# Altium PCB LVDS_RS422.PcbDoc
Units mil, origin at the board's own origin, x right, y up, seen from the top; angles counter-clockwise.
Board outline 3925 x 2090 mil, 4 copper layers (Top Layer, GROUND, VCC, Bottom Layer); 100 components, 102 nets, 610 pads, 149 vias.
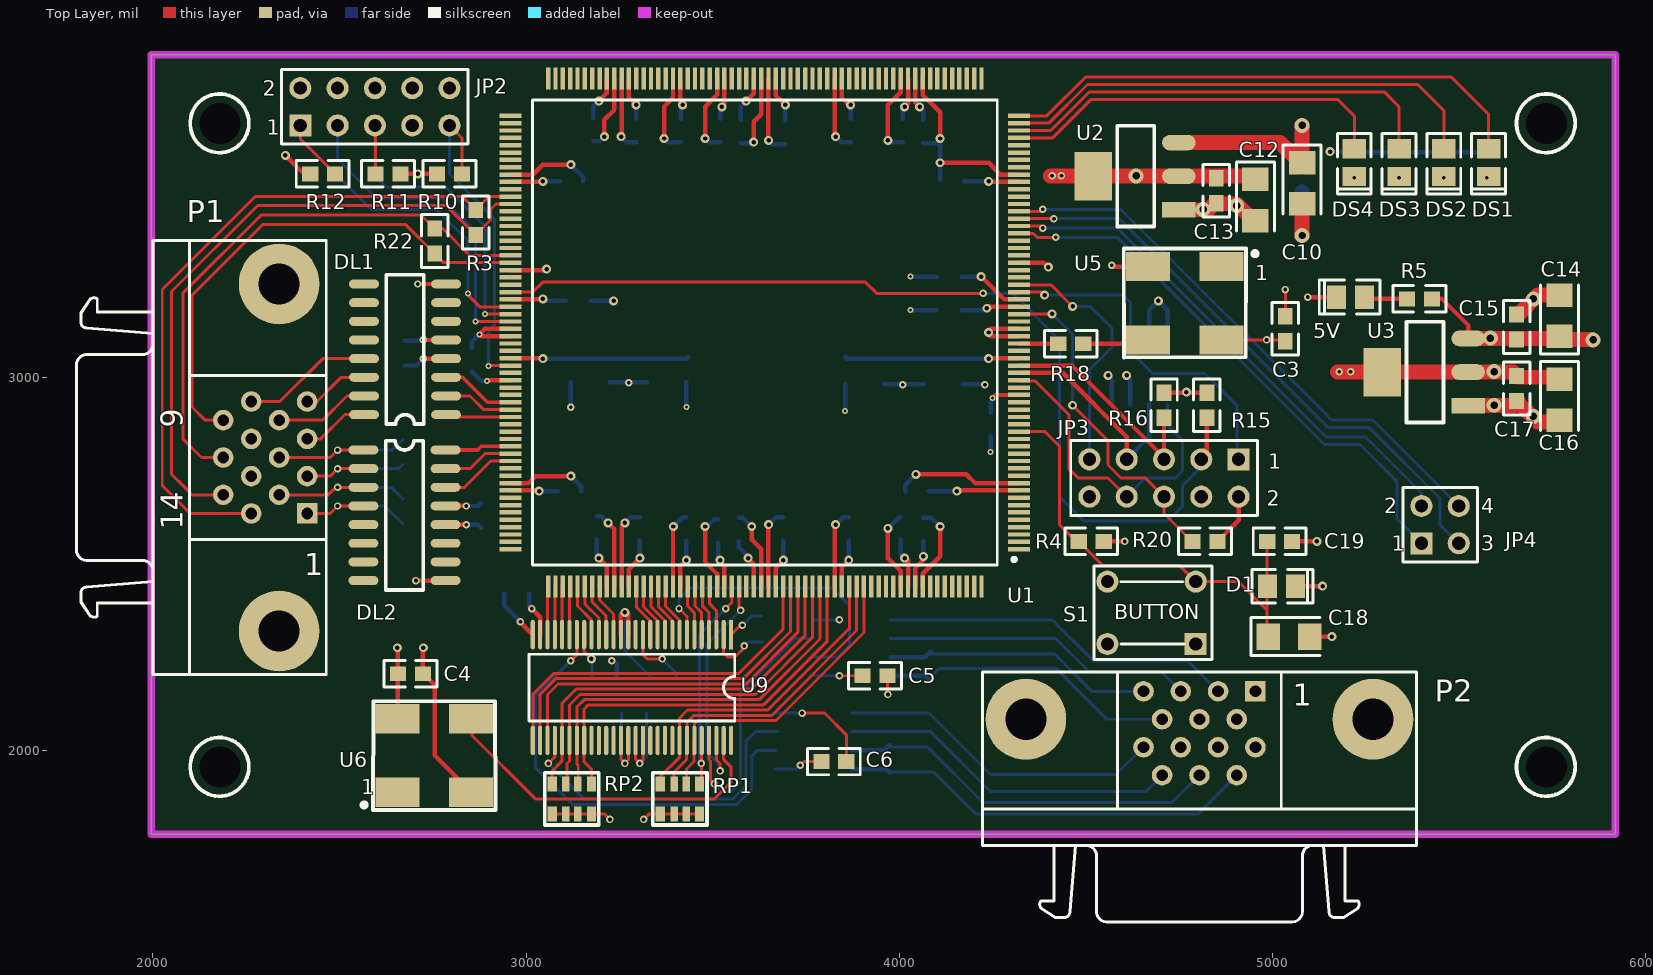
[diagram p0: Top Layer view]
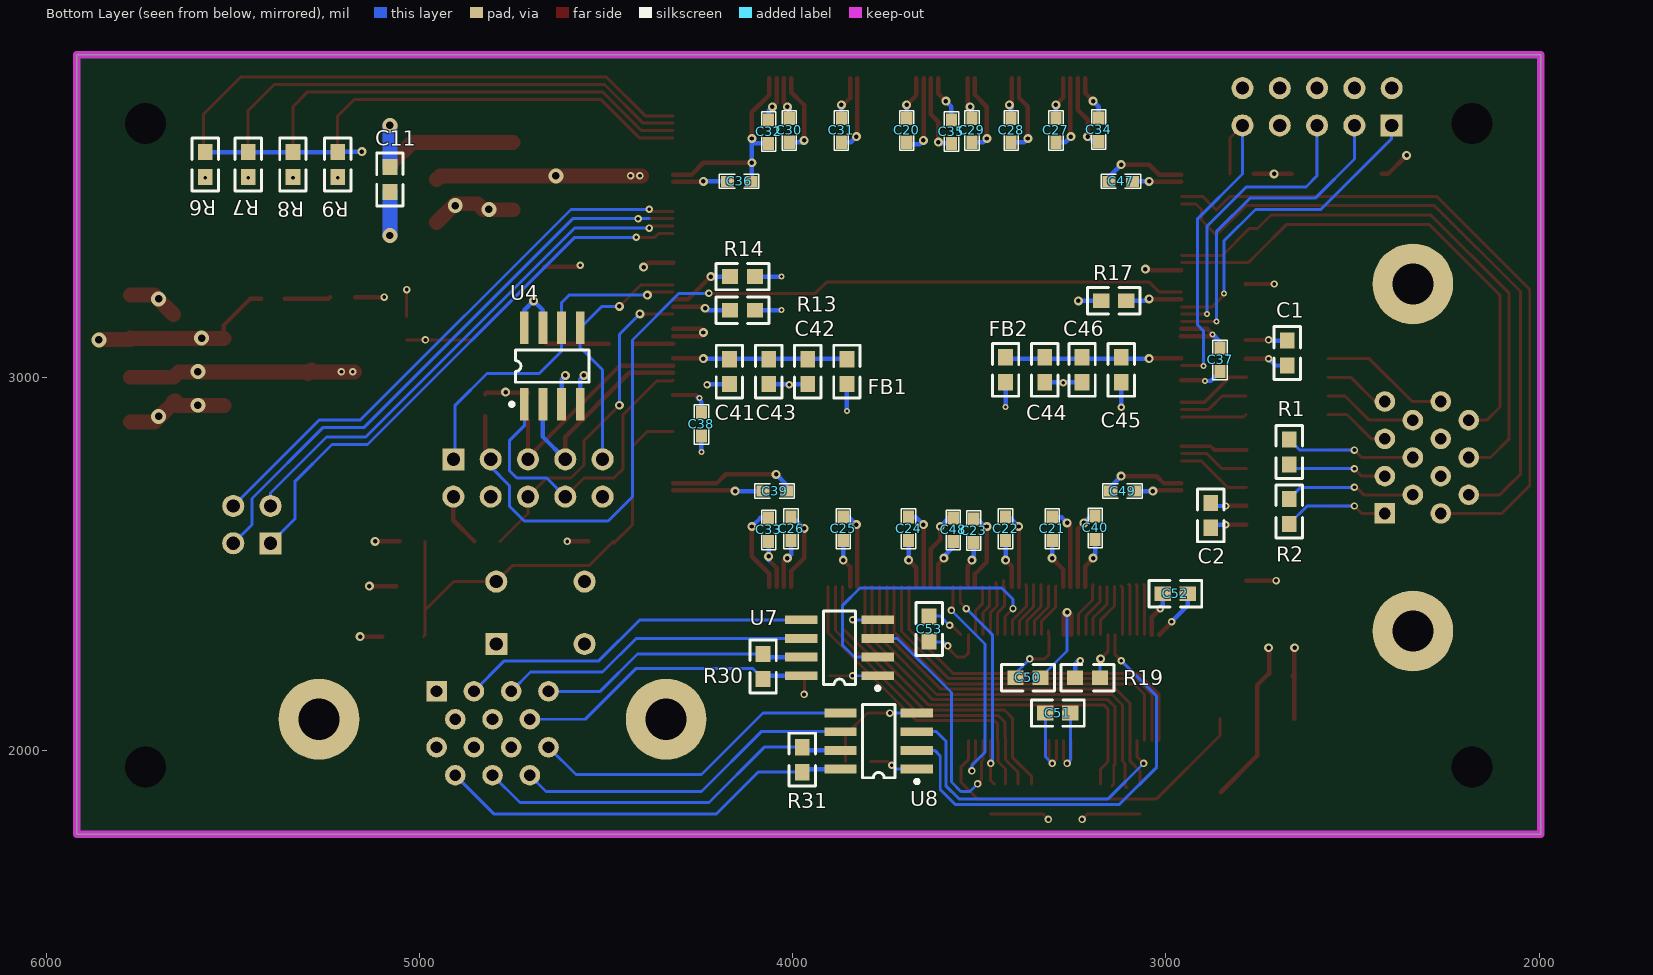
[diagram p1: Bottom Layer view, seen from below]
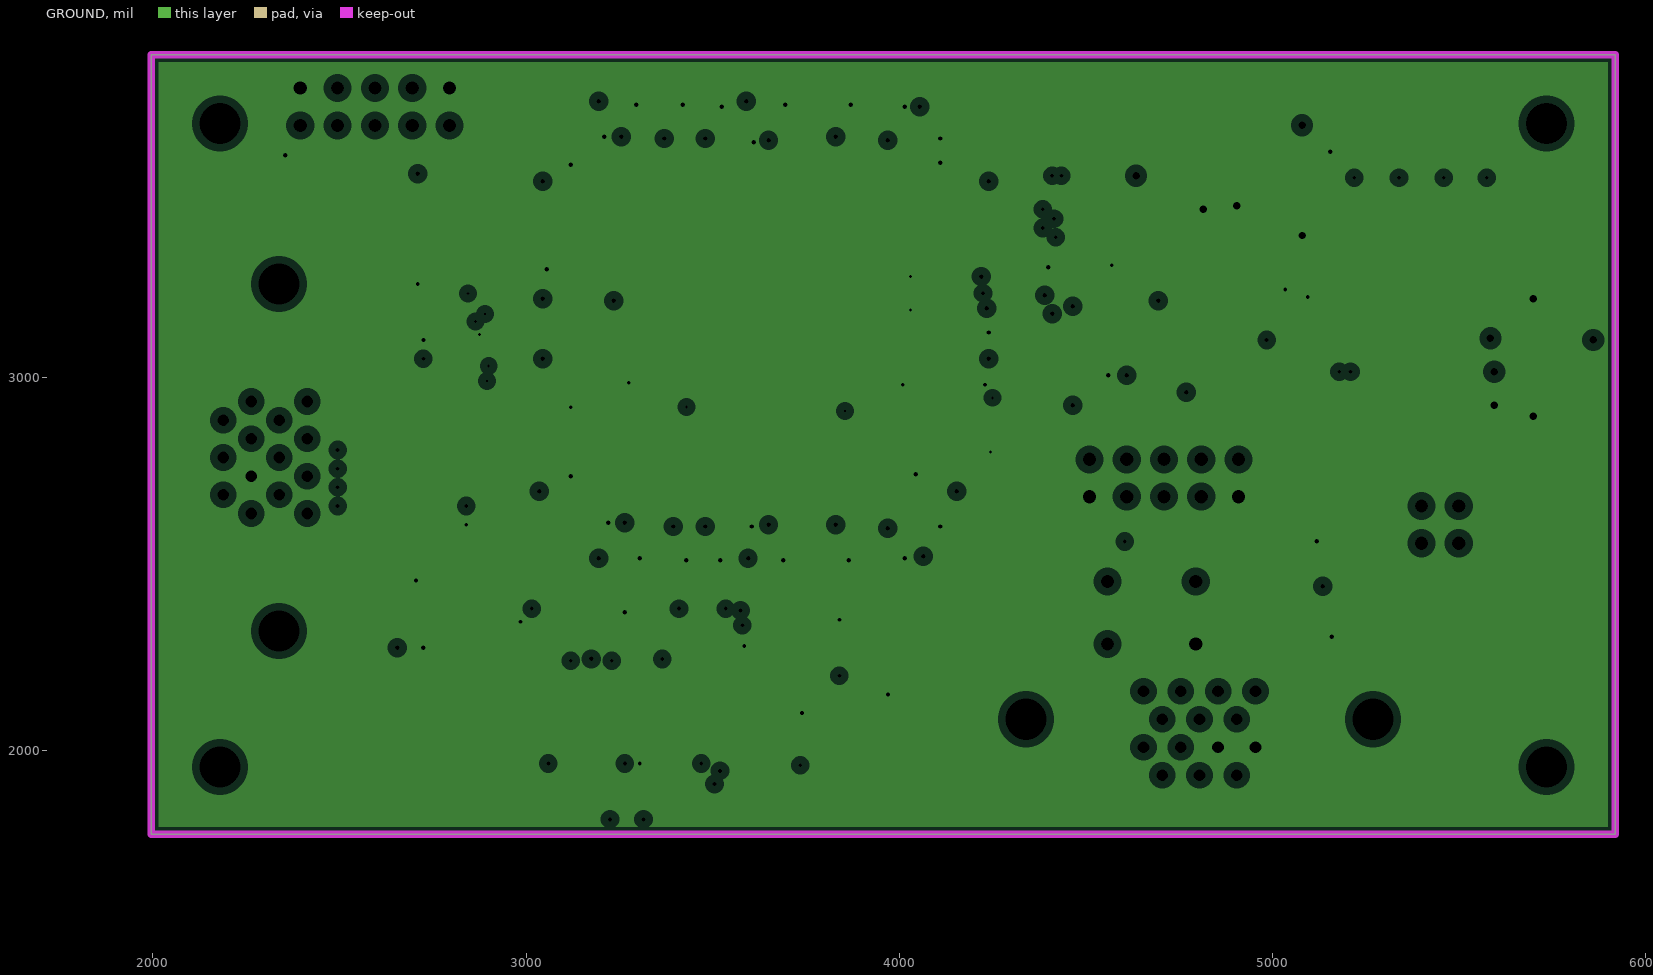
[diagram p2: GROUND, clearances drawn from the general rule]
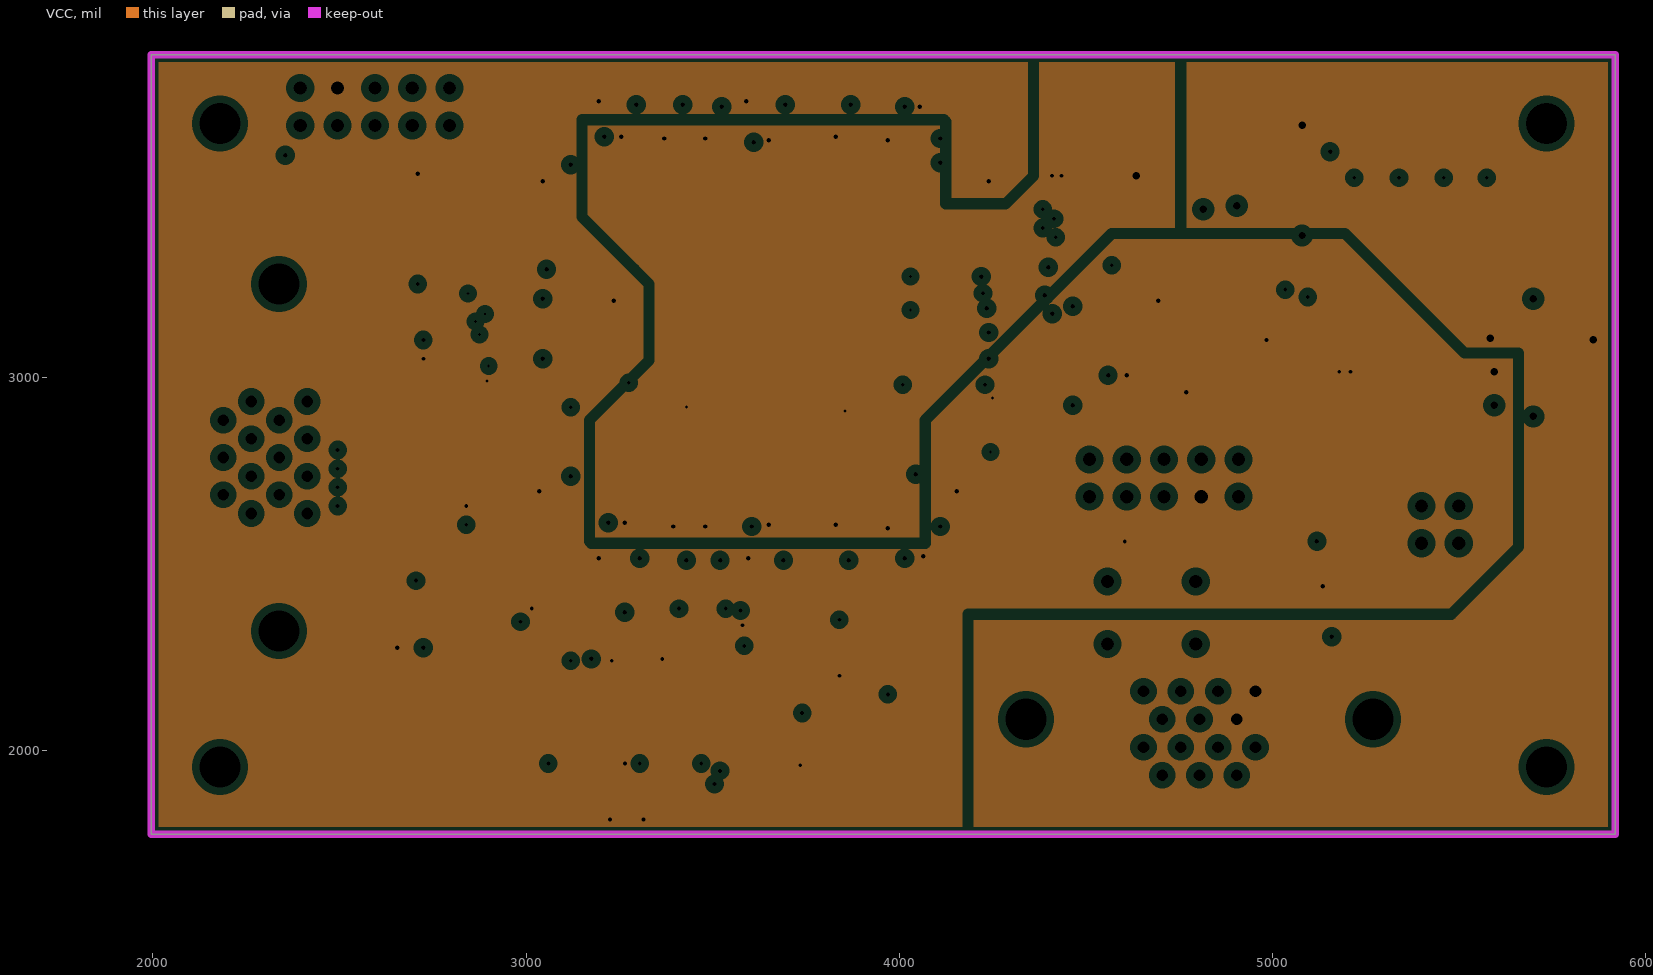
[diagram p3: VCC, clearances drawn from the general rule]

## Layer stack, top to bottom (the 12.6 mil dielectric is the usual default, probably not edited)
Top Layer: signal copper 1.4
Dielectric: core 12.6, FR-4, Dk 4.8
GROUND: plane copper 1.4, net GND
Dielectric: prepreg 12.6, FR-4, Dk 4.8
VCC: plane copper 1.4, net (Multiple Nets)
Dielectric: core 12.6, FR-4, Dk 4.8
Bottom Layer: signal copper 1.4

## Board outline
1995,1775 5920,1775 5920,3865 1995,3865

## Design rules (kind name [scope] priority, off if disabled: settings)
Clearance [All] p1: gap=6
PlaneClearance [All] p1: clearance=20
PlaneConnect [All] p1: planeconnectstyle=Relief reliefexpansion=20 reliefentries=4 reliefconductorwidth=10 reliefairgap=10
PolygonConnect [All] p1: connectstyle=Relief reliefconductorwidth=10 reliefentries=4 polygonreliefangle="90 Angle"
RoutingVias [All] p1: holewidth=28 width=50 viastyle="Through Hole" minholewidth=28 minwidth=50 maxholewidth=28 maxwidth=50
SilkscreenOverComponentPads [All] p1: minsilkscreentomaskgap=10
SolderMaskExpansion [All] p1: expansion=4
TestPointUsage FabricationTestPointUsage [All] p1: valid=0 allowmultiple=FALSE
Testpoint FabricationTestpoint [All] p1: side=3 testpointundercomponent=TRUE minsize=40 maxsize=100 preferedsize=60 minholesize=0 maxholesize=40 preferedholesize=32 testpointgrid=1 style=297 order=0-112345678
Width [All] p1: maxlimit=50 minlimit=6 preferedwidth=10
21 further rules are at their usual default settings.

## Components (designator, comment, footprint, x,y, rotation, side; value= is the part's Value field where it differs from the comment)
5V "LED3" "SMD _LED" 5210,3215 r0 top (schematic designator DS5)
C1 "0.1uF" C1608-0603 2675,3065 r90 bottom
C2 "0.1uF" C1608-0603 2880,2630 r270 bottom
C3 "Cap" C1608-0603 5035,3130 r270 top
C4 "0.1uF" C1608-0603 2690,2205 r0 top
C5 "0.1uF" C1608-0603 3935,2200 r0 top
C6 "0.1uF" C1608-0603 3825,1970 r0 top
C10 "Cap Pol1" CC3216-1206 5080,3520 r270 top
C11 "Cap" C1608-0603 5080,3530 r90 bottom
C12 "Cap Pol1" CC3216-1206 4955,3475 r270 top
C13 "Cap" C1608-0603 4850,3500 r90 top
C14 "Cap Pol1" CC3216-1206 5770,3165 r90 top
C15 "Cap" C1608-0603 5655,3135 r270 top
C16 "Cap Pol1" CC3216-1206 5770,2940 r270 top
C17 "Cap" C1608-0603 5655,2970 r90 top
C18 "22uF" CC3216-1206 5045,2305 r0 top
C19 "0.1uF" C1608-0603 5020,2560 r180 top
C20 "Cap" 0603 3695,3630 r90 bottom
C21 "Cap" 0603 3305,2625 r270 bottom
C22 "Cap" 0603 3430,2625 r270 bottom
C23 "Cap" 0603 3515,2620 r270 bottom
C24 "Cap" 0603 3690,2625 r270 bottom
C25 "Cap" 0603 3865,2625 r270 bottom
C26 "Cap" 0603 4005,2625 r270 bottom
C27 "Cap" 0603 3295,3630 r90 bottom
C28 "Cap" 0603 3415,3630 r90 bottom
C29 "Cap" 0603 3520,3630 r90 bottom
C30 "Cap" 0603 4010,3630 r90 bottom
C31 "Cap" 0603 3870,3630 r90 bottom
C32 "Cap" 0603 4065,3690 r270 bottom
C33 "Cap" 0603 4065,2560 r90 bottom
C34 "Cap" 0603 3180,3695 r270 bottom
C35 "Cap" 0603 3575,3690 r270 bottom
C36 "Cap" 0603 4175,3525 r180 bottom
C37 "Cap" 0603 2855,3015 r90 bottom
C38 "Cap" 0603 4245,2905 r270 bottom
C39 "Cap" 0603 4080,2695 r180 bottom
C40 "Cap" 0603 3190,2565 r90 bottom
C41 "Cap Pol1" C1608-0603 4170,3015 r270 bottom
C42 "Cap" C1608-0603 3960,3015 r90 bottom
C43 "Cap" C1608-0603 4065,3015 r90 bottom
C44 "Cap Pol1" C1608-0603 3325,3020 r270 bottom
C45 "Cap" C1608-0603 3120,3020 r90 bottom
C46 "Cap" C1608-0603 3225,3020 r90 bottom
C47 "Cap" 0603 3090,3525 r0 bottom
C48 "Cap" 0603 3570,2560 r90 bottom
C49 "Cap" 0603 3085,2695 r0 bottom
C50 "0.1uF" C1608-0603 3370,2195 r0 bottom
C51 "0.1uF" C1608-0603 3290,2100 r180 bottom
C52 "0.1uF" C1608-0603 2975,2420 r0 bottom
C53 "0.1uF" C1608-0603 3635,2325 r90 bottom
D1 "Diode" "SMD _LED" 5025,2440 r180 top
DL1 "DS90LV047" SO-16 2785,2900 r180 top
DL2 "DS90LV048" SO-16 2565,2805 r0 top
DS1 "LED2" "SMD _LED" 5580,3575 r90 top
DS2 "LED2" "SMD _LED" 5460,3575 r90 top
DS3 "LED2" "SMD _LED" 5340,3575 r90 top
DS4 "LED2" "SMD _LED" 5220,3575 r90 top
FB1 "FB" C1608-0603 3855,3015 r90 bottom
FB2 "FB" C1608-0603 3430,3020 r90 bottom
JP2 "JTAG" HDR2X5 2395,3675 r0 top
JP3 "AS mode" HDR2X5 4910,2780 r180 top
JP4 "Header 2X2" HDR2X2 5400,2555 r0 top
P1 "Header 14" CHAMP1.27-2H14A 2000,2785 r90 top
P2 "Header 14" CHAMP1.27-2H14A 4805,1745 r180 top
R1 "" CR1608-0603 2670,2800 r270 bottom
R2 "" CR1608-0603 2670,2640 r270 bottom
R3 "Res2" C1608-0603 2865,3415 r270 top
R4 "1K" CR1608-0603 4515,2560 r0 top
R5 "Res2" CR1608-0603 5395,3210 r0 top
R6 "Res2" C1608-0603 5575,3570 r90 bottom
R7 "Res2" C1608-0603 5460,3570 r90 bottom
R8 "Res2" C1608-0603 5340,3570 r90 bottom
R9 "Res2" C1608-0603 5220,3570 r90 bottom
R10 "Res2" C1608-0603 2795,3545 r180 top
R11 "Res2" C1608-0603 2630,3545 r0 top
R12 "Res2" C1608-0603 2455,3545 r0 top
R13 "Res2" C1608-0603 4135,3180 r0 bottom
R14 "Res2" C1608-0603 4135,3270 r0 bottom
R15 "Res2" C1608-0603 4825,2925 r90 top
R16 "Res2" C1608-0603 4710,2925 r90 top
R17 "Res2" C1608-0603 3140,3205 r0 bottom
R18 "Res2" C1608-0603 4460,3090 r180 top
R19 "10K" CR1608-0603 3210,2195 r180 bottom
R20 "Res2" C1608-0603 4820,2560 r180 top
R22 "Res2" C1608-0603 2755,3365 r270 top
R30 "120" CR1608-0603 4080,2225 r90 bottom
R31 "120" CR1608-0603 3975,1975 r90 bottom
RP1 "470" RP8 3365,1830 r90 top
RP2 "470" RP8 3075,1830 r90 top
S1 "SW" BUTTON 4645,2335 r90 top
U1 "EP1C12Q240C6" PQFP240 3640,3120 r180 top
U2 "AS1117-1.5V" LM1117 4500,3590 r180 top
U3 "AS1117-1.5V" LM1117 5275,3065 r180 top
U4 "EPCS1SI8" SOIC8 4645,3030 r180 bottom
U5 "Oscillator   20MHz" OSC 4780,3100 r270 top
U6 "CRYSTAL  32M" OSC 2740,2085 r90 top
U7 "MAX3077EESA" SO-G8 3875,2275 r90 bottom
U8 "MAX3077EESA" SO-G8 3770,2025 r90 bottom
U9 "SC28L202A1DGG" TSSOP56 3550,2310 r270 top

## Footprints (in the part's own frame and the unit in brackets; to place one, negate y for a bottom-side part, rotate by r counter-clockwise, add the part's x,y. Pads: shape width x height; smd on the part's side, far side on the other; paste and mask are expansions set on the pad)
0603 [mil] "for DSP"
  rect 35x30 smd: 1(0,0) 2(62.99,0)
  silkscreen extent -22,-19 84,19
BUTTON [mm]
  rect 1.5x1.5 hole 0.9: 1(-1.27,-3.81)
  round 1.5 hole 0.9: 2(2.98,-3.81) 3(2.98,2.2) 4(-1.27,2.2)
  silkscreen extent -2.34,-4.93 4.04,3.12
C1608-0603 [mm]
  rect 1.1x1 smd: 1(-0.85,0) 2(0.85,0)
  silkscreen extent -1.8,-0.9 1.8,0.9
CC3216-1206 [mm]
  rect 1.6x1.8 smd: 1(-1.4,0) 2(1.4,0)
  silkscreen extent -2.6,-1.3 2.1,1.3
CHAMP1.27-2H14A [mm] "Connector; 14 Position; Right Angle; Pitch 1.27 mm"
  rect 1.4x1.4 hole 0.8: 1(-3.81,-10.5)
  round 1.4 hole 0.8: 2(-2.54,-8.595) 3(-1.27,-10.5) 4(0,-8.595) 5(1.27,-10.5) 6(2.54,-8.595) 7(3.81,-10.5) 8(3.81,-6.69) 9(2.54,-4.785) 10(1.27,-6.69) 11(0,-4.785) 12(-1.27,-6.69) 13(-2.54,-4.785) 14(-3.81,-6.69)
  round 5.5 hole 2.8: 15(-11.82,-8.595) 16(11.82,-8.595)
  silkscreen extent -14.77,-11.8 14.77,5.2
CR1608-0603 [mm]
  rect 1.1x1 smd: 1(-0.85,0) 2(0.85,0)
  silkscreen extent -1.8,-0.9 1.8,0.9
HDR2X2 [mm] "Connector; Header; 2x2 Position"
  rect 1.5x1.5 hole 0.9: 1(0,0)
  round 1.5 hole 0.9: 2(0,2.54) 3(2.54,0) 4(2.54,2.54)
  silkscreen extent -1.27,-1.27 3.81,3.81
HDR2X5 [mm] "Connector; Header; 5x2 Position"
  rect 1.5x1.5 hole 0.9: 1(0,0)
  round 1.5 hole 0.9: 2(0,2.54) 3(2.54,0) 4(2.54,2.54) 5(5.08,0) 6(5.08,2.54) 7(7.62,0) 8(7.62,2.54) 9(10.16,0) 10(10.16,2.54)
  silkscreen extent -1.27,-1.27 11.43,3.81
LM1117 [mil]
  rect 90x42 smd: 1(-250,141)
  oval 90x42 smd: 2(-250,51) 3(-250,-39)
  rect 100x130 smd: 2(-20,51)
  silkscreen extent -184,-84 -85,186
OSC [mm]
  rect 2x3 smd: 1(-5,2.134) 2(-5,-2.87) 3(0,-2.866) 4(0,2.134)
  silkscreen extent -6.22,-4.52 1.19,4.48
PQFP240 [mm] "byTX chaned for cyclone FPGA"
  rect 1.5x0.3 smd: 1(-17.3,14.75) 2(-17.3,14.25) 3(-17.3,13.75) 4(-17.3,13.25) 5(-17.3,12.75) 6(-17.3,12.25) 7(-17.3,11.75) 8(-17.3,11.25) 9(-17.3,10.75) 10(-17.3,10.25) 11(-17.3,9.75) 12(-17.3,9.25) 13(-17.3,8.75) 14(-17.3,8.25) 15(-17.3,7.75) 16(-17.3,7.25) 17(-17.3,6.75) 18(-17.3,6.25) 19(-17.3,5.75) 20(-17.3,5.25) 21(-17.3,4.75) 22(-17.3,4.25) 23(-17.3,3.75) 24(-17.3,3.25) 25(-17.3,2.75) 26(-17.3,2.25) 27(-17.3,1.75) 28(-17.3,1.25) 29(-17.3,0.75) 30(-17.3,0.25) 31(-17.3,-0.25) 32(-17.3,-0.75) 33(-17.3,-1.25) 34(-17.3,-1.75) 35(-17.3,-2.25) 36(-17.3,-2.75) 37(-17.3,-3.25) 38(-17.3,-3.75) 39(-17.3,-4.25) 40(-17.3,-4.75) 41(-17.3,-5.25) 42(-17.3,-5.75) 43(-17.3,-6.25) 44(-17.3,-6.75) 45(-17.3,-7.25) 46(-17.3,-7.75) 47(-17.3,-8.25) 48(-17.3,-8.75) 49(-17.3,-9.25) 50(-17.3,-9.75) 51(-17.3,-10.25) 52(-17.3,-10.75) 53(-17.3,-11.25) 54(-17.3,-11.75) 55(-17.3,-12.25) 56(-17.3,-12.75) 57(-17.3,-13.25) 58(-17.3,-13.75) 59(-17.3,-14.25) 60(-17.3,-14.75) 121(17.3,-14.75) 122(17.3,-14.25) 123(17.3,-13.75) 124(17.3,-13.25) 125(17.3,-12.75) 126(17.3,-12.25) 127(17.3,-11.75) 128(17.3,-11.25) 129(17.3,-10.75) 130(17.3,-10.25) 131(17.3,-9.75) 132(17.3,-9.25) 133(17.3,-8.75) 134(17.3,-8.25) 135(17.3,-7.75) 136(17.3,-7.25) 137(17.3,-6.75) 138(17.3,-6.25) 139(17.3,-5.75) 140(17.3,-5.25) 141(17.3,-4.75) 142(17.3,-4.25) 143(17.3,-3.75) 144(17.3,-3.25) 145(17.3,-2.75) 146(17.3,-2.25) 147(17.3,-1.75) 148(17.3,-1.25) 149(17.3,-0.75) 150(17.3,-0.25) 151(17.3,0.25) 152(17.3,0.75) 153(17.3,1.25) 154(17.3,1.75) 155(17.3,2.25) 156(17.3,2.75) 157(17.3,3.25) 158(17.3,3.75) 159(17.3,4.25) 160(17.3,4.75) 161(17.3,5.25) 162(17.3,5.75) 163(17.3,6.25) 164(17.3,6.75) 165(17.3,7.25) 166(17.3,7.75) 167(17.3,8.25) 168(17.3,8.75) 169(17.3,9.25) 170(17.3,9.75) 171(17.3,10.25) 172(17.3,10.75) 173(17.3,11.25) 174(17.3,11.75) 175(17.3,12.25) 176(17.3,12.75) 177(17.3,13.25) 178(17.3,13.75) 179(17.3,14.25) 180(17.3,14.75)
  rect 0.3x1.5 smd: 61(-14.75,-17.3) 62(-14.25,-17.3) 63(-13.75,-17.3) 64(-13.25,-17.3) 65(-12.75,-17.3) 66(-12.25,-17.3) 67(-11.75,-17.3) 68(-11.25,-17.3) 69(-10.75,-17.3) 70(-10.25,-17.3) 71(-9.75,-17.3) 72(-9.25,-17.3) 73(-8.75,-17.3) 74(-8.25,-17.3) 75(-7.75,-17.3) 76(-7.25,-17.3) 77(-6.75,-17.3) 78(-6.25,-17.3) 79(-5.75,-17.3) 80(-5.25,-17.3) 81(-4.75,-17.3) 82(-4.25,-17.3) 83(-3.75,-17.3) 84(-3.25,-17.3) 85(-2.75,-17.3) 86(-2.25,-17.3) 87(-1.75,-17.3) 88(-1.25,-17.3) 89(-0.75,-17.3) 90(-0.25,-17.3) 91(0.25,-17.3) 92(0.75,-17.3) 93(1.25,-17.3) 94(1.75,-17.3) 95(2.25,-17.3) 96(2.75,-17.3) 97(3.25,-17.3) 98(3.75,-17.3) 99(4.25,-17.3) 100(4.75,-17.3) 101(5.25,-17.3) 102(5.75,-17.3) 103(6.25,-17.3) 104(6.75,-17.3) 105(7.25,-17.3) 106(7.75,-17.3) 107(8.25,-17.3) 108(8.75,-17.3) 109(9.25,-17.3) 110(9.75,-17.3) 111(10.25,-17.3) 112(10.75,-17.3) 113(11.25,-17.3) 114(11.75,-17.3) 115(12.25,-17.3) 116(12.75,-17.3) 117(13.25,-17.3) 118(13.75,-17.3) 119(14.25,-17.3) 120(14.75,-17.3) 181(14.75,17.3) 182(14.25,17.3) 183(13.75,17.3) 184(13.25,17.3) 185(12.75,17.3) 186(12.25,17.3) 187(11.75,17.3) 188(11.25,17.3) 189(10.75,17.3) 190(10.25,17.3) 191(9.75,17.3) 192(9.25,17.3) 193(8.75,17.3) 194(8.25,17.3) 195(7.75,17.3) 196(7.25,17.3) 197(6.75,17.3) 198(6.25,17.3) 199(5.75,17.3) 200(5.25,17.3) 201(4.75,17.3) 202(4.25,17.3) 203(3.75,17.3) 204(3.25,17.3) 205(2.75,17.3) 206(2.25,17.3) 207(1.75,17.3) 208(1.25,17.3) 209(0.75,17.3) 210(0.25,17.3) 211(-0.25,17.3) 212(-0.75,17.3) 213(-1.25,17.3) 214(-1.75,17.3) 215(-2.25,17.3) 216(-2.75,17.3) 217(-3.25,17.3) 218(-3.75,17.3) 219(-4.25,17.3) 220(-4.75,17.3) 221(-5.25,17.3) 222(-5.75,17.3) 223(-6.25,17.3) 224(-6.75,17.3) 225(-7.25,17.3) 226(-7.75,17.3) 227(-8.25,17.3) 228(-8.75,17.3) 229(-9.25,17.3) 230(-9.75,17.3) 231(-10.25,17.3) 232(-10.75,17.3) 233(-11.25,17.3) 234(-11.75,17.3) 235(-12.25,17.3) 236(-12.75,17.3) 237(-13.25,17.3) 238(-13.75,17.3) 239(-14.25,17.3) 240(-14.75,17.3)
  silkscreen extent -17.1,-15.83 15.83,15.83
RP8 [mil]
  rect 40x25 smd: 1(0,5) 8(80,5)
  rect 40x20 smd: 2(0,-32) 3(0,-64) 6(80,-64) 7(80,-32)
  rect 40x24 smd: 4(0,-100) 5(80,-100)
  silkscreen extent -30,-120 110,25
"SMD _LED" [mm]
  rect 1.3x1.6 smd: 1(0.95,0) 2(-0.95,0)
  silkscreen extent -2.13,-1.15 2,1.15
SO-16 [mil]
  oval 80x24 smd: 1(-0.7,0.1) 2(-0.7,-49.9) 3(-0.7,-99.9) 4(-0.7,-149.9) 5(-0.7,-199.9) 6(-0.7,-249.9) 7(-0.7,-299.9) 8(-0.7,-349.9) 9(219.3,-349.9) 10(219.3,-299.9) 11(219.3,-249.9) 12(219.3,-199.9) 13(219.3,-149.9) 14(219.3,-99.9) 15(219.3,-49.9) 16(219.3,0.1)
  silkscreen extent 59,-375 159,25
SO-G8 [mm]
  rect 0.6x2.2 smd: 1(-1.905,-2.6) 2(-0.635,-2.6) 3(0.635,-2.6) 4(1.905,-2.6) 5(1.905,2.6) 6(0.635,2.6) 7(-0.635,2.6) 8(-1.905,2.6)
  silkscreen extent -2.88,-2.72 2.5,1.1
SOIC8 [mm] "8-Pin Small-Outline Integrated Circuit (SOIC)"
  rect 0.6x2.2 smd: 1(-1.905,-2.6) 2(-0.635,-2.6) 3(0.635,-2.6) 4(1.905,-2.6) 5(1.905,2.6) 6(0.635,2.6) 7(-0.635,2.6) 8(-1.905,2.6)
  silkscreen extent -2.88,-2.72 2.5,1.1
TSSOP56 [mm]
  rect 2x0.28 smd: 1(-0.003,-0.01)
  oval 2x0.28 smd: 2(-0.003,-0.51) 3(-0.003,-1.01) 4(-0.003,-1.51) 5(-0.003,-2.01) 6(-0.003,-2.51) 7(-0.003,-3.01) 8(-0.003,-3.51) 9(-0.003,-4.01) 10(-0.003,-4.51) 11(-0.003,-5.01) 12(-0.003,-5.51) 13(-0.003,-6.01) 14(-0.003,-6.51) 15(-0.003,-7.01) 16(-0.003,-7.51) 17(-0.003,-8.01) 18(-0.003,-8.51) 19(-0.003,-9.01) 20(-0.003,-9.51) 21(-0.003,-10.01) 22(-0.003,-10.51) 23(-0.003,-11.01) 24(-0.003,-11.51) 25(-0.003,-12.01) 26(-0.003,-12.51) 27(-0.003,-13.01) 28(-0.003,-13.51) 29(7.197,-13.51) 30(7.197,-13.01) 31(7.197,-12.51) 32(7.197,-12.01) 33(7.197,-11.51) 34(7.197,-11.01) 35(7.197,-10.51) 36(7.197,-10.01) 37(7.197,-9.51) 38(7.197,-9.01) 39(7.197,-8.51) 40(7.197,-8.01) 41(7.197,-7.51) 42(7.197,-7.01) 43(7.197,-6.51) 44(7.197,-6.01) 45(7.197,-5.51) 46(7.197,-5.01) 47(7.197,-4.51) 48(7.197,-4.01) 49(7.197,-3.51) 50(7.197,-3.01) 51(7.197,-2.51) 52(7.197,-2.01) 53(7.197,-1.51) 54(7.197,-1.01) 55(7.197,-0.51) 56(7.197,-0.01)
  silkscreen extent 1.33,-13.76 5.86,0.24

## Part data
5V: "Typical BLUE SiC LED"
C1 C2 C4 C5 C6 C19 C50 C51 C52 C53: library part Cap, "Capacitor"
C3 C11 C13 C15 C17 C20 C21 C22 C23 C24 C25 C26 C27 C28 C29 C30 C31 C32 C33 C34 C35 C36 C37 C38 C39 C40 C42 C43 C45 C46 C47 C48 C49: "Capacitor"
C10 C12 C14 C16 C41 C44: "Polarized Capacitor (Radial)"
C18: library part "Cap Pol3", "Polarized Capacitor (Surface Mount)"
D1: "Default Diode"
DS1 DS2 DS3 DS4: "Typical RED, GREEN, YELLOW, AMBER GaAs LED"
FB1 FB2: library part Inductor, "Inductor"
JP2 JP3: library part "Header 5X2", "Header, 5-Pin, Dual row"
JP4: "Header, 2-Pin, Dual row"
P1 P2: "Header, 14-Pin"
R1 R2: library part Res1, "Resistor"
R3 R5 R6 R7 R8 R9 R10 R11 R12 R13 R14 R15 R16 R17 R18 R20 R22: "Resistor"
R4 R19 R30 R31: library part Res2, "Resistor"
RP1 RP2: library part RESPACK8
S1: "Switch"
U1: "Cyclone Family, 1.5V FPGA, 173 I/O Pins, 2 x PLLs, Commercial Grade, Speed Grade 6"
U2 U3: library part "Volt Reg", "Voltage Regulator"
U4: "EPCS1 Series, In-system programmable 3.3V configuration device, 8-Pin SOIC, 1-Megabit, Industrial Grade"
U5: library part Oscillator
U6: library part CRYSTAL4
U7 U8: library part MAX3077E
U9: library part SC28L202

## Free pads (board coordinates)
  round 50 hole 110: 2(2180,1955) 2(2180,3680) 2(5735,1955) 2(5735,3680)

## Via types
v1: diameter 24, hole 12, Top Layer to Bottom Layer, 71 vias
v2: diameter 20, hole 10, Top Layer to Bottom Layer, 55 vias
v3: diameter 16, hole 8, Top Layer to Bottom Layer, 12 vias
v4: diameter 40, hole 20, Top Layer to Bottom Layer, 11 vias

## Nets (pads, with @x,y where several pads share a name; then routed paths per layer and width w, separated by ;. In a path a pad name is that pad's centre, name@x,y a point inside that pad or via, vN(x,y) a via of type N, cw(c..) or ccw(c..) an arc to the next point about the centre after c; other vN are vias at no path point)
A0: U1.182 U9.25 | length 136.1
  Top Layer w8: U9.25 3077.18,2442.18 U1.182@3080,2445
A1: U1.183 U9.24 | length 136.2
  Top Layer w8: U9.24 3096.87,2441.87 U1.183@3100,2445
A2: U1.184 U9.23 | length 131.3
  Top Layer w8: U9.23 3116.55,2436.55 U1.184@3120,2440
A2A: P2.6 R30.1 U7.8 | length 800.2
  Bottom Layer w8: R30.1 4108.46,2220 4420,2220 4556.61,2083.39 P2.6
  Bottom Layer w12: U7.8 4070,2200 R30.1@4080,2190
A2B: P2.7 R30.2 U7.7 | length 858.7
  Bottom Layer w8: R30.2 4416.54,2258.46 4515,2160 4516.61,2158.39 P2.7 4526.61,2158.39
  Bottom Layer w12: U7.7 4070,2250 R30.2@4085,2265
A2Y: P2.3 U7.5 | length 969.5
  Bottom Layer w8: U7.5 4410,2350 4520,2240 4685,2240 ; 4697.5,2240 4685,2240 ; P2.3 4773.39,2240 4685,2240
A2Z: P2.5 U7.6 | length 836.3
  Bottom Layer w8: U7.6 4420,2300 4510,2210 4703.39,2210 P2.5
A3: U1.200 U9.6 | length 152.3
  Top Layer w8: U1.200 3433.31,2386.69 3451.2,2368.8 U9.6 ; U1.200@3435,2438.9 U1.200@3435,2455
A4: U1.201 U9.5 | length 147.3
  Top Layer w8: U1.201 3452.99,2387.01 3470.88,2369.12 U9.5 ; U1.201@3455,2438.9 U1.201@3455,2450
A5: U1.202 U9.4 | length 136.2
  Top Layer w8: U1.202 3472.68,2387.32 3490.57,2369.43 U9.4
A6: U1.203 U9.3 | length 131.2
  Top Layer w8: U1.203 3492.36,2392.64 3510,2375 U9.3@3510,2315
AS_CONFDN: JP3.3 R15.1 U1.145 | length 2606.8
  Top Layer w8: U1.145 3018.27,3228.27 3045,3255 3910,3255 3940,3225 v2(4225,3225)
  Top Layer w12: JP3.3 4825,2795 R15.1 R15.1@4825,2895
  Bottom Layer w8: v2(4225,3225) 4305,3225 4430,3100 4430,2680 4495,2615 4720,2615 4760,2655 4760,2710 4810,2760 JP3.3
AS_DCLK: JP3.1 U1.36 U4.6 | length 935.7
  Top Layer w8: U1.36 4381.73,3228.27 v1(4390,3220)
  Bottom Layer w8: v1@4385,3220 v1(4390,3220) 4600,3220 4620,3200 U4.6 4620,3070 4680,3010 4820,3010 4905,2925 JP3.1@4905,2780
AS_NCONFIG: JP3.5 R16.1 U1.26 | length 603
  Top Layer w12: U1.26 4463.58,3031.42 JP3.5@4710,2785 ; JP3.5 JP3.5@4710,2785 ; R16.1@4715,2890 4710,2885 JP3.5@4710,2785
B2A: P2.13 R31.1 U8.8 | length 1130.8
  Bottom Layer w8: R31.1 4093.46,1941.54 4205,1830 4495,1830 ; 4500,1830 4495,1830 ; P2.13 4801.61,1830 4495,1830
  Bottom Layer w12: U8.8 3965,1950 R31.1@3975,1940
B2B: P2.11 R31.2 U8.7 | length 1030.7
  Bottom Layer w8: R31.2 4076.54,2008.46 4225,1860 4731.61,1860 P2.11
  Bottom Layer w12: U8.7 3960,2000 R31.2@3975,2015
B2Y: P2.8 U8.5 | length 896.4
  Bottom Layer w8: U8.5 4080,2100 4245,1935 4475,1935 ; 4490,1935 4475,1935 ; P2.8 4581.61,1935 4475,1935
B2Z: P2.9 U8.6 | length 916.9
  Bottom Layer w8: U8.6 4085,2050 4245,1890 4661.61,1890 P2.9
CEN: U1.213 U9.29 | length 980.7
  Top Layer w8: U9.29 3018.13,2150 3074.13,2206 3570,2206 3689.21,2325.21 U1.213
D0: U1.185 U9.20 | length 144.1
  Top Layer w8: U1.185 3138.03,2386.97 3147.27,2377.73 3165.76,2359.24 3175,2350 U9.20@3175,2320 ; U9.20 U9.20@3175.61,2320
D1: U1.186 U9.19 | length 144.4
  Top Layer w8: U1.186 3157.72,2392.28 3195.29,2354.71 U9.19
D2: U1.187 U9.18 | length 144.4
  Top Layer w8: U1.187 3177.4,2397.6 3214.98,2360.02 U9.18
D3: U1.188 U9.17 | length 150.5
  Top Layer w8: U1.188@3195,2438.9 U1.188@3195,2445 ; U1.188 3197.09,2402.91 3234.66,2365.34 U9.17
D4: U1.193 U9.12 | length 145.2
  Top Layer w8: 3295,2385 3333.09,2346.91 U9.12 ; U1.193@3295,2438.9 U1.193@3295,2440 ; 3295.51,2385.51 U1.193
D5: U1.194 U9.11 | length 145.6
  Top Layer w8: U1.194@3315,2438.9 U1.194@3315,2440 ; U1.194 3315.2,2385.2 3315,2385 3315,2384.8 3352.77,2347.03 U9.11
D6: U1.195 U9.10 | length 150.5
  Top Layer w8: U1.195 3334.88,2385.12 3372.46,2347.54 U9.10 ; U1.195@3335,2438.9 U1.195@3335,2445
D7: U1.196 U9.9 | length 150.5
  Top Layer w8: U1.196 3354.57,2385.43 3392.14,2347.86 U9.9 ; U1.196@3355,2438.9 U1.196@3355,2445
DATA: JP3.7 U1.25 U4.2 | length 592.5
  Top Layer w12: U1.25 4438.27,3011.73 4610,2840 JP3.7
  Bottom Layer w12: JP3.7 4670,2840 U4.2
EN1: DL1.1 U1.162 | length 175.8
  Top Layer w8: DL1.1 2791.98,2893.62 U1.162
EN2: DL2.16 U1.166 | length 178.6
  Top Layer w10: DL2.16 2870.1,2805.1 2879.88,2814.88 U1.166
FPGA_ASDO: JP3.9 U1.37 U4.5 | length 674
  Top Layer w8: U1.37 4407.05,3247.95 v1(4465,3190)
  Bottom Layer w8: v1(4465,3190) 4512.36,3190 U4.5 4570,3080 4510,3020 JP3.9
FPGA_IO18: DS1.1 U1.60 | length 1436.1
  Top Layer w8: U1.60 4395.71,3700.71 4500,3805 5480,3805 5580,3705 DS1.1
FPGA_IO19: DS2.1 U1.59 | length 1313.6
  Top Layer w8: U1.59 4401.02,3681.02 4505,3785 5390,3785 5460,3715 DS2.1
FPGA_IO20: DS3.1 U1.58 | length 1191
  Top Layer w8: U1.58 4406.34,3661.34 4510,3765 5300,3765 5340,3725 DS3.1
FPGA_IO21: DS4.1 U1.57 | length 1047.9
  Top Layer w8: U1.57 4411.65,3641.65 4515,3745 5175,3745 5220,3700 DS4.1
FPGA_IO41: JP4.1 U1.44 | length 1481.6
  Top Layer w8: U1.44 4321.85,3385 4360,3385 4370,3375 v2(4420,3375)
  Bottom Layer w8: v2(4420,3375) 4585,3375 5140,2820 5235,2820 5335,2720 5335,2620 JP4.1
FPGA_IO42: JP4.2 U1.45 | length 1495.2
  Top Layer w8: U1.45 4379.57,3405.43 v2(4385,3400)
  Bottom Layer w8: v2(4385,3400) 4585,3400 5145,2840 5235,2840 ; 5150,2840 5235,2840 ; JP4.2 5400,2690 5250,2840 5235,2840
FPGA_IO43: JP4.3 U1.46 | length 1610.3
  Top Layer w8: U1.46 4414.88,3425.12 v2(4415,3425)
  Bottom Layer w8: 4385,3425 4590,3425 5150,2865 5260,2865 5450,2675 5450,2605 JP4.3
FPGA_IO44: JP4.4 U1.47 | length 1515.4
  Top Layer w8: U1.47 4379.8,3444.8 v2(4385,3450)
  Bottom Layer w8: v2@4380,3450 v2(4385,3450) 4595,3450 5160,2885 5270,2885 JP4.4
FPGA_NCSO: JP3.8 U1.24 U4.1 | length 876.3
  Top Layer w8: U1.24 4323.15,2990 4365,2990 4455,2900 4455,2755 4480,2730 4560,2730 JP3.8
  Bottom Layer w8: JP3.8 4660,2730 4740,2730 4760,2750 4760,2830 4720,2870 U4.1
GCLK1: R18.2 U1.29 | length 109.1
  Top Layer w8: R18.2@4429.53,3090.47 R18.2@4430,3090
  Top Layer w12: U1.29 R18.2@4429.53,3090.47
GND: 5V.2 C1.2 C2.2 C3.1 C4.2 C5.2 C6.2 C10.2 C11.1 C12.2 C13.1 C14.2 C15.1 C16.2 C17.1 C18.2 C19.1 C20.2 C21.2 C22.2 C23.2 C24.2 C25.2 C26.2 C27.2 C28.2 C29.2 C30.2 C31.2 C32.2 C33.2 C34.2 C35.2 C36.2 C37.2 C38.2 C39.2 C40.2 C41.2 C42.1 C43.1 C44.2 C45.1 C46.1 C47.2 C48.2 C49.2 C50.1 C51.1 C52.1 C53.1 DL1.5 DL1.8 DL2.9 DL2.12 JP2.2 JP2.10 JP3.2 JP3.10 P1.12 P2.12 P2.14 R6.2 R7.2 R8.2 R9.2 R12.1 R13.1 R14.1 R20.1 S1.1 U1.10 U1.30 U1.31 U1.40 U1.52 U1.69 U1.71 U1.80 U1.89 U1.91 U1.96 U1.102 U1.109 U1.111 U1.129 U1.142 U1.150 U1.151 U1.171 U1.190 U1.192 U1.199 U1.205 U1.210 U1.212 U1.221 U1.230 U1.232 U2.1 U3.1 U4.4 U5.2 U6.2 U7.4 U8.4 U9.2 U9.15 U9.16 U9.28 U9.43 U9.44 | length 9118.3
  Top Layer w8: U9.43 3293.72,1976.28 3302.5,1967.5 3307.5,1967.5 3313.4,1973.4 U9.44 ; U9.2 3529.94,2260.06 3540,2250 3560,2250 v2@3585,2275 ; v2(3740,2100) 3800,2100 3858.46,2041.54 C6.2 ; v2@3968.46,2146.54 C5.2 ; C3.1 v2(5035,3235)
  Top Layer w12: v1(2355,3595) 2405,3545 R12.1 ; v2@2705.1,2455.1 DL2.9 ; v2(2710,3250) 2785.6,3250 DL1.8 ; C4.2 v1@2723.46,2273.46 ; v2@2724.9,3099.9 DL1.5 ; C4.2@2725,2205 2755,2175 2755,1986.15 U6.2 ; DL2.12 2839.9,2605.1 v2(2840,2605) ; v3(2875,3115) 2880,3110 U1.151@2960,3110 ; v3@2880,3120 2889.84,3129.84 U1.150 ; U1.171 3006.46,2716.46 3025,2735 v1(3120,2735) ; U1.142 v1@3057.32,3287.32 ; U1.129 3018.23,3543.23 3045,3570 v1(3120,3570) ; v2@2983.23,2345 U9.28 ; v1(3210,3645) 3210,3690 3236.46,3716.46 U1.111 ; v1@3222.5,2607.5 3236.46,2593.54 U1.190 ; U9.16 3254.35,2364.35 3265,2375 3274.03,2365.97 U9.15 ; U1.192 3275.83,2485.83 v1(3305,2515) ; U1.109 3275.83,3749.17 v1(3295,3730) ; U1.199 3413.62,2493.62 v1(3430,2510) ; U1.102 3413.62,3736.38 v1(3420,3730) v1@3425,3725 ; v1@3520,2505 3531.73,2493.27 U1.205 ; v1@3531.73,3731.73 U1.96 ; v1(3605,2600) 3605,2565 3625,2545 ; v1(3610,3630) 3610,3685 3630.16,3705.16 U1.91 ; 3615,2555 3625,2545 ; U1.210 3630.16,2539.84 3625,2545 ; U1.212 3669.53,2489.53 v1(3690,2510) ; U1.89 3669.53,3755.47 v1(3695,3730) ; U1.221 3846.69,2491.69 v1(3865,2510) ; U1.80 3846.69,3748.31 v1@3870,3725 ; U1.230 v1@4023.86,2510 ; 4023.86,3733.86 U1.71 ; v1(4045,2740) 4180,2740 4203.54,2716.46 U1.10 ; U1.232 4063.23,2473.23 4110,2520 v1(4110,2600) ; U1.69 4063.23,3756.77 4110,3710 v1(4110,3640) ; v1(4110,3575) 4240,3575 4271.77,3543.23 U1.52 ; U1.30 4244.84,3110.16 4235,3120 4244.84,3129.84 U1.31 ; U1.40 4387.99,3307.01 v1(4400,3295) ; v2@4566.85,3296.85 U5.2 ; R20.1 4910,2616.54 JP3.2 JP3.2@4910,2685 ; C19.1 v1(5120,2560) ; v2(5095,3215) 5V.2 ; C18.2 v1(5160,2305)
  Top Layer w40: U2.1 4829,3449 4845,3465 4905,3465 C12.2@4955,3415 ; v4(5080,3380) C10.2 ; U3.1 5649,2924 C17.1@5660,2935 ; C17.1 5658.27,2933.27 5698.27,2893.27 5711.54,2880 C16.2@5775,2880 ; C15.1@5660,3168.46 5711.54,3220 C14.2@5775,3220
  Bottom Layer w8: v1(3265,2370) 3265,2266.54 C50.1 ; v2(3305,1965) 3323.46,1983.46 C51.1 ; v2(3585,2280) 3595,2290 C53.1@3635,2290 ; U8.4 v2(3740,2100) ; U7.4 v2(3840,2350)
  Bottom Layer w12: C1.2 v2@2723.46,3098.46 ; v2(2840,2605) 2871.54,2605 C2.2 ; C37.2 2855,3095 v3(2875,3115) ; C52.1 2941.54,2388.46 v2(2985,2345) ; v1(3120,2735) 3147.99,2707.01 C49.2 ; v2(3120,2920) C45.1 ; v1(3120,3570) 3152.99,3537.01 C47.2 ; C34.2 3197.01,3632.01 v1(3210,3645) ; C40.2 3202.01,2627.99 v1(3220,2610) ; C46.1 C44.2 ; C27.2 v1(3295,3730) v1@3295,3735 ; v1(3305,2515) C21.2 ; C28.2 v1@3415,3725 ; v1(3430,2510) C22.2 ; C23.2 3515,2520 v1@3525,2510 ; C29.2 3520,3715 v1@3530,3725 ; C48.2 3582.01,2622.99 v1(3605,2600) ; C35.2 3607.01,3627.01 v1(3610,3630) ; v1(3690,2510) C24.2 ; C20.2@3695,3687.99 v1(3695,3730) ; v1(3865,2510) C25.2 ; C31.2 v1(3870,3730) v1@3870,3735 ; C42.1 C43.1 ; C26.2@4005,2565 C26.2 4005,2525 v1(4015,2515) ; C30.2 4010,3720 v1(4015,3725) ; C39.2 4017.01,2712.01 v1(4045,2740) ; v3(4030,3180) R13.1 ; v3(4030,3270) R14.1 ; C33.2 4087.01,2622.99 v1(4110,2600) ; C32.2 4102.01,3627.01 4110,3635 v1(4110,3575) C36.2@4110,3530 ; C41.2 v2@4228.46,2981.54 ; v3(4245,2800) C38.2 ; v1(4560,3005) 4570,2995 U4.4 ; v1(5155,3605) 5218.46,3605 R9.2 R8.2 R7.2 R6.2 R6.2@5580,3603.46
  Bottom Layer w40: v4(5080,3380) C11.1
  other v1: 2725,2275 3520,2510 4240,3120 3055,3290 3525,3725
  other v2: 3970,2150 2705,2455 4010,2980 4230,2980 3275,2985 2725,3100 4570,3300
  other v4: 5700,2895 5595,2925 5700,3210 4815,3450 4905,3460
GP04: U1.13
GP05: U1.14
GP06: U1.15
GP07: U1.16
I/M: R19.2 U9.21 | length 128.6
  Top Layer w8: U9.21 3155.92,2264.08 v1(3175,2245)
  Bottom Layer w8: v1@3175,2250 3176.54,2248.46 R19.2
IACKN: U1.181 U9.26 | length 135.9
  Top Layer w8: U9.26 3057.5,2442.5 U1.181@3060,2445
IO0A: RP1.5 U1.206 U9.52 | length 632.9
  Top Layer w8: RP1.5@3460,1910 3470.88,1920.88 U9.52 ; v2(3535,2380) 3551.42,2396.42 U1.206
  Bottom Layer w8: v2(3470,1965) 3465,1970 3465,2310 v2(3535,2380)
IO1A: RP1.6 U1.224 U9.51 | length 849
  Top Layer w8: RP1.6@3430,1910 3430,1950 3450,1970 3450,2025.44 U9.51 3451.2,2071.2 3460,2080 3670,2080 3905.75,2315.75 U1.224
IO2A: RP1.7 U1.223 U9.50 | length 853.3
  Top Layer w8: RP1.7 3397,1942 3430,1975 U9.50@3430,2035 ; U9.50@3431.51,2035 3431.51,2075.51 3450,2094 3659,2094 3886.06,2321.06 U1.223
IO3A: RP1.8 U1.222 U9.49 | length 864.6
  Top Layer w8: RP1.8 3360,1930 3411.83,1981.83 U9.49 3411.83,2086.83 3433,2108 3648,2108 3866.38,2326.38 U1.222
IO4B: RP2.5 U1.219 U9.36 | length 1081.9
  Top Layer w8: RP2.5 3175,1950 3155.92,1969.08 U9.36 3155.92,2110.92 3167,2122 3637,2122 3807.32,2292.32 U1.219
IO5B: RP2.6 U1.218 U9.35 | length 1082.1
  Top Layer w8: RP2.6@3145,1905 3140,1910 3140,1960 3136.24,1963.76 U9.35 3136.24,2116.24 3156,2136 3625,2136 3787.64,2298.64 U1.218
IO6B: RP2.7 U1.217 U9.34 | length 1088.8
  Top Layer w8: RP2.7@3105,1900 3110,1905 3110,1965 3116.55,1971.55 U9.34 3116.55,2121.55 3145,2150 3615,2150 3767.95,2302.95 U1.217
IO7B: RP2.8 U1.216 U9.33 | length 1085.2
  Top Layer w8: RP2.8 3070,1945 3096.87,1971.87 U9.33 3096.87,2126.87 3134,2164 3604,2164 3748.27,2308.27 U1.216
IRQN: U1.207 U9.54 | length 633
  Top Layer w8: U9.54 3510.25,1974.75 3520,1965 v2(3520,1945) ; U1.207 3571.1,2378.9 v2(3575,2375)
  Bottom Layer w8: v2(3520,1945) 3520,1960 3485,1995 3485,2285 v2(3575,2375)
JTAG_TCK: JP2.1 R12.2 U1.147 | length 1039.4
  Top Layer w8: JP2.1 2395,3638.46 R12.2 ; v3(2845,3225) 2845,3220 2876.1,3188.9 U1.147
  Bottom Layer w8: JP2.1 2395,3640 2585,3450 2760,3450 2845,3365 v3(2845,3225)
JTAG_TDI: JP2.9 R10.1 U1.155 | length 904.3
  Top Layer w8: JP2.9 2828.46,3641.54 R10.1 ; v3(2900,3030) 2901.42,3031.42 U1.155
  Bottom Layer w8: JP2.9 2795,3545 2915,3425 2915,3140 2900,3125 v3(2900,3030)
JTAG_TDO: JP2.3 U1.149 | length 874.7
  Top Layer w8: v3@2865,3149.53 U1.149
  Bottom Layer w8: JP2.3 2495,3585 2600,3480 2775,3480 2865,3390 v3@2865,3155 ; v3(2865,3150) v3@2870,3150
JTAG_TMS: JP2.5 R11.1 U1.148 | length 920.8
  Top Layer w8: R11.1 JP2.5@2596.54,3673.46 ; v3(2890,3170) 2890.79,3169.21 U1.148
  Top Layer w12: JP2.5 JP2.5@2596.54,3673.46
  Bottom Layer w8: JP2.5 2595,3540 2625,3510 2785,3510 2890,3405 v3(2890,3170)
LVDS1_INCLKN: P1.11 R22.1 U1.140 | length 1529.8
  Top Layer w8: P1.11 2130,2785 2080,2835 2080,3225 2290,3435 2718.46,3435 R22.1 2776.54,3398.46 2848.31,3326.69 U1.140
LVDS1_INCLKP: P1.9 R22.2 U1.141 | length 1403.1
  Top Layer w8: P1.9 2140,2885 2105,2920 2105,3220 2295,3410 2360,3410 ; 2330,3410 2360,3410 ; U1.141 2779.53,3307.01 R22.2 2676.54,3410 2360,3410
LVDS1_INDATAN: P1.14 R3.1 U1.132 | length 1861.8
  Top Layer w8: P1.14 2100,2635 2025,2710 2025,3235 2275,3485 2828.46,3485 R3.1 2900.71,3484.17 U1.132
LVDS1_INDATAP: P1.13 R3.2 U1.133 | length 1805.1
  Top Layer w8: 2100,2690 2085,2705 ; P1.13 2105,2685 2085,2705 ; 2305,3460 2350,3460 ; U1.133 2919.49,3464.49 2905,3450 2905,3421.54 R3.2 2786.54,3460 2350,3460 ; 2085,2705 2050,2740 2050,3230 2280,3460 2350,3460
LVIN1+: DL2.2 P1.3 R1.2 | length 339
  Top Layer w8: P1.3 2475,2735 v2(2495,2755) 2495.1,2755.1 DL2.2
  Bottom Layer w8: v2(2495,2755) 2658.46,2755 R1.2
LVIN1-: DL2.1 P1.4 R1.1 | length 421
  Top Layer w8: P1.4 2475,2785 v2(2495,2805) 2495.1,2805.1 DL2.1
  Bottom Layer w8: v2(2495,2805) 2641.54,2805 R1.1
LVIN2+: DL2.3 P1.2 R2.1 | length 422.3
  Top Layer w8: P1.2 2470,2685 2490.1,2705.1 DL2.3
  Bottom Layer w8: v2(2495,2705) 2638.46,2705 R2.1
LVIN2-: DL2.4 P1.1 R2.2 | length 354.3
  Top Layer w8: P1.1 2475,2635 v2(2495,2655) 2495.1,2655.1 DL2.4
  Bottom Layer w8: v2(2495,2655) 2621.54,2655 R2.2
LVOUT1+: DL1.15 P1.6 | length 254.2
  Top Layer w8: P1.6 2455,2885 2519.9,2949.9 DL1.15
LVOUT1-: DL1.16 P1.5 | length 179.2
  Top Layer w8: P1.5 2450,2835 2514.9,2899.9 DL1.16
LVOUT2+: DL1.14 P1.7 | length 179.2
  Top Layer w8: P1.7 2440,2935 2504.9,2999.9 DL1.14
LVOUT2-: DL1.13 P1.8 | length 349.9
  Top Layer w8: P1.8 2340,2935 2454.9,3049.9 DL1.13
NCE: JP3.6 R20.2 U1.33 | length 893.1
  Top Layer w8: U1.33 v1@4410.79,3169.21 ; v1(4465,2925) 4560,2830 4560,2765 4595,2730 4660,2730 JP3.6 4710,2635 R20.2@4785,2560
  Bottom Layer w8: v1(4410,3170) 4465,3115 v1(4465,2925)
NCEO: U1.32
NetDS1_2: DS1.2 R6.1
  other v2: 5575,3535
NetDS2_2: DS2.2 R7.1
  other v2: 5460,3535
NetDS3_2: DS3.2 R8.1
  other v2: 5340,3535
NetDS4_2: DS4.2 R9.1
  other v2: 5220,3535
NetDS5_1: 5V.1 R5.1 | length 123.6
  Top Layer w12: 5V.1@5240,3215 5245,3210 R5.1
NetR13_2: R13.2 U1.34 | length 150.8
  Top Layer w12: v1@4238.9,3188.9 U1.34
  Bottom Layer w12: R13.2 4230,3180 v1(4235,3185)
NetR14_2: R14.2 U1.35 | length 181
  Top Layer w12: v1(4220,3270) 4220,3265 4225,3265 4281.42,3208.58 U1.35
  Bottom Layer w12: R14.2 v1(4220,3270)
NetR18_1: R18.1 U5.3 | length 173.6
  Top Layer w12: R18.1 4660,3090 U5.3@4665,3095
NSTATUS: R17.1 U1.146 | length 148.3
  Top Layer w12: U1.146 v1@3043.58,3208.58
  Bottom Layer w12: v1(3045,3210) 3050,3205 R17.1
RDN: U1.215 U9.31 | length 985.6
  Top Layer w8: U9.31 3057.5,2149.7 3085.8,2178 3590,2178 3728.58,2316.58 U1.215
RST: U1.197 U9.8 | length 150.5
  Top Layer w8: U1.197 3374.25,2385.75 3411.83,2348.17 U9.8 ; U1.197@3375,2438.9 U1.197@3375,2445
RXDA: U7.2 U9.7 | length 823.8
  Top Layer w8: v2(3410,2380) 3431.51,2358.49 U9.7
  Bottom Layer w8: v2(3410,2380) 3410,2405 3440,2435 3820,2435 3867.5,2387.5 3867.5,2282.5 3835,2250 U7.2 ; U7.2@3767.64,2255 U7.2 ; U7.2@3770,2250 U7.2 ; U7.2@3780,2250 U7.2
RXDB: U8.2 U9.22 | length 1200.4
  Top Layer w8: v2(3120,2240) 3136.24,2256.24 U9.22
  Bottom Layer w8: v2(3120,2240) 3025,2145 3025,1955 3125,1855 3565,1855 3605,1895 3605,1985 3620,2000 U8.2 U8.2@3670,2000
SCLK: U6.3 U9.55 | length 949
  Top Layer w8: U6.3@2855,2085 2855,2040 3025,1870 3505,1870 3550,1915 3550,1955 3529.94,1975.06 U9.55
SYSTEM_RESET#: C18.1 C19.2 D1.1 R4.1 S1.2 U1.17 | length 1243.9
  Top Layer w8: U1.17 4390.75,2854.25 4430,2815 4430,2605 R4.1@4480,2555 ; R4.1 4546.54,2495 4752.32,2495 S1.2 4909.21,2452.32 4986.54,2375 ; C19.2 4986.54,2375 ; C18.1 4986.54,2308.35 4986.54,2375
TTLIN1: DL2.15 U1.167 | length 191.2
  Top Layer w8: DL2.15 2850.1,2755.1 2890.2,2795.2 U1.167
TTLIN2: DL2.14 U1.168 | length 203.8
  Top Layer w8: DL2.14 2835.1,2705.1 2905.51,2775.51 U1.168
TTLOUT1: DL1.2 U1.161 | length 188.4
  Top Layer w8: DL1.2 2850.1,2949.9 2882.91,2917.09 2886.69,2913.31 U1.161
TTLOUT2: DL1.3 U1.160 | length 200.9
  Top Layer w10: DL1.3 2830.1,2999.9 2897.01,2932.99 U1.160
TXDA: U7.3 U9.53 | length 786.2
  Top Layer w8: U9.53 3490.57,1974.43 3495,1970 3495,1920 v2(3505,1910)
  Bottom Layer w8: v2(3505,1910) 3525,1890 3550,1890 3575,1915 3575,2155 3710,2290 ; 3650,2230 3710,2290 ; U7.3@3765,2300 3720,2300 3710,2290
TXDB: U8.3 U9.32 | length 868
  Top Layer w8: v2(3060,1965) 3077.18,1982.18 U9.32
  Bottom Layer w8: v2(3060,1965) 3155,1870 3555,1870 3590,1905 3590,2025 3615,2050 U8.3 U8.3@3675,2050
V1.5: C12.1 C13.2 C20.1 C21.1 C22.1 C23.1 C24.1 C25.1 C26.1 C27.1 C28.1 C29.1 C30.1 C31.1 FB1.1 FB2.1 U1.72 U1.81 U1.90 U1.97 U1.103 U1.110 U1.191 U1.198 U1.204 U1.211 U1.220 U1.229 U2.2 | length 3275.3
  Top Layer w12: U1.191 3256.14,2601.14 v1(3265,2610) ; v1@3256.14,3641.14 U1.110 ; v1(3370,3640) 3370,3725 3393.94,3748.94 U1.103 ; U1.198 v1@3393.94,2603.94 ; v1(3480,2600) 3480,2505 3512.05,2472.95 U1.204 ; v1(3480,3640) 3480,3725 3512.05,3757.05 U1.97 ; U1.211 v1@3649.84,2604.84 ; v1@3649.84,3635 U1.90 ; U1.220 v1@3827.01,2607.99 ; v1@3827.01,3642.01 U1.81 ; v1(3970,2595) 3970,2515 4004.17,2480.83 U1.229 ; v1(3970,3635) 3970,3730 4004.17,3764.17 U1.72
  Top Layer w40: v2@4405,3540 4519,3540 4520,3539 4750,3539 4946,3539 C12.1@4955,3530
  Bottom Layer w12: v1(3255,3645) 3270,3630 C27.1 ; v1(3265,2610) 3280,2625 C21.1 ; v1(3370,3640) 3380,3630 C28.1 ; v1(3395,2600) 3420,2625 C22.1 ; v3(3430,2920) FB2.1 ; v1@3480,2595 3505,2620 C23.1 ; v1(3480,3640) 3490,3630 C29.1 ; v1(3650,2605) 3670,2625 C24.1 ; v1(3650,3635) 3660,3625 C20.1@3695,3625 ; v1(3830,2605) 3850,2625 C25.1 ; v1(3830,3645) 3845,3630 C31.1 ; v3(3855,2910) FB1.1 ; v1(3970,2595) 4000,2625 C26.1 ; v1(3970,3635) 3975,3630 C30.1
  other v2: 4410,3540 4435,3540
  other v4: 4635,3540
V3.3: C1.1 C2.1 C3.2 C4.1 C5.1 C6.1 C16.1 C17.2 C32.1 C33.1 C34.1 C35.1 C36.1 C37.1 C38.1 C39.1 C40.1 C47.1 C48.1 C49.1 C50.2 C51.2 C52.2 C53.2 D1.2 DL1.4 DL2.13 JP2.4 JP3.4 R4.2 R10.2 R11.2 R15.2 R16.2 R17.2 R19.1 RP1.1 RP1.2 RP1.3 RP1.4 RP2.1 RP2.2 RP2.3 RP2.4 U1.9 U1.22 U1.51 U1.70 U1.92 U1.112 U1.130 U1.157 U1.172 U1.189 U1.209 U1.231 U3.2 U4.3 U4.7 U4.8 U5.4 U6.4 U7.1 U8.1 U9.1 U9.13 U9.27 U9.41 U9.42 | length 4851.6
  Top Layer w8: RP2.1 RP2.2 RP2.3 RP2.4 3210,1830 v2(3225,1815) ; U9.41 3254.35,1975.65 v2(3265,1965) 3275,1975 U9.42@3275,2026.64 ; U9.13 3313.4,2256.6 3325,2245 v2(3365,2245) ; v2(3315,1815) 3330,1830 RP1.1 RP1.2 RP1.3 RP1.4 RP1.4@3470,1830 ; U9.13@3315,2310.1 U9.13@3315,2320 ; U9.1 3574.52,2335 v2(3580,2335) ; v2(3735,1960) 3745,1970 C6.1 ; v2(3840,2200) C5.1@3900,2200 ; U5.4 C3.2@5035,3100
  Top Layer w10: v3(4250,2945) 4257.68,2952.68 U1.22
  Top Layer w12: C4.1@2655,2205 C4.1@2656,2204 ; U6.4 C4.1@2656,2204 ; C4.1 v1@2656.54,2276.54 ; C4.1@2660,2200 C4.1@2656,2204 ; R11.2 R10.2 R10.2@2765,3545 ; v2(2725,3050) 2785.6,3050 DL1.4 ; DL2.13 v2@2839.9,2655.1 ; v3@2892.95,2992.05 U1.157 ; U1.172 v1@3036.77,2696.77 ; U1.130 v1@3043.54,3523.54 ; v2(3015,2380) 3037.81,2357.19 U9.27 ; v1(3195,2515) 3216.77,2493.23 U1.189 ; v1(3195,3740) 3216.77,3761.77 U1.112 ; v1(3590,3740) 3610.47,3760.47 U1.92 ; v1(3595,2515) 3610.47,2499.53 U1.209 ; U1.231 4043.54,2488.54 4065,2510 v1(4065,2520) ; U1.70 4043.54,3736.46 v1(4055,3725) ; v1@4155,2696.77 U1.9 ; v1@4236.46,3523.54 U1.51 ; R4.2 v2(4605,2560) ; R16.2 4821.54,2958.46 R15.2@4825,2955 ; D1.2 v1(5135,2440)
  Top Layer w40: v2@5175,3014 U3.2@5295,3014 ; U3.2@5290,3020 U3.2@5296,3014 ; U3.2@5300,3010 U3.2@5296,3014 ; C16.1@5775,3000 5660,3000 5646,3014 5525,3014 U3.2@5296,3014
  Bottom Layer w8: C51.2 3256.54,1973.46 v2(3265,1965) ; v2(3365,2245) 3403.46,2206.54 C50.2 ; v2(3580,2335) 3605,2360 C53.2@3630,2360 ; U8.1 3725,1950 v2(3735,1960) ; U7.1 v2(3840,2200)
  Bottom Layer w12: C1.1 2706.54,3031.54 v2(2725,3050) ; v2(2840,2655) 2871.54,2655 C2.1 ; C37.1 2880,2990 v3(2895,2990) ; C52.2 3008.46,2386.54 v2(3015,2380) ; v1(3035,2695) C49.1 ; v1(3045,3525) C47.1 ; R17.2 v1(3235,3205) ; C34.1 3180,3725 v1(3195,3740) v1@3200,3745 ; C40.1 3190,2525 v1@3200,2515 ; v2(3230,2240) 3235,2240 3243.46,2231.54 R19.1 ; C48.1 3570,2545 v1@3600,2515 ; C35.1 3575,3725 v1(3590,3740) ; v1(4055,3725) 4065,3715 C32.1 ; v1@4065,2510 C33.1 ; C39.1 4150,2695 v1@4155,2700 ; C36.1 v1(4240,3525) ; C38.1 4245,2935 v3@4255,2945 ; v1(4610,3005) 4620,2995 U4.3 ; U4.7 4670,3180 v1(4695,3205) 4720,3180 U4.8@4720,3135
  other v1: 2655,2275 4155,2695 4770,2960 2710,3545
  other v2: 5180,3015 5210,3015 4985,3100
  other v4: 5595,3015
V5: C10.1 C11.2 C14.1 C15.2 P2.1 P2.2 R5.2 U2.3 U3.3 | length 1057.7
  Top Layer w12: R5.2@5425,3210 R5.2 5455,3210 5525,3140 U3.3
  Top Layer w40: U2.3 5021,3629 C10.1@5075,3575 ; C10.1 v4(5080,3675) ; U3.3 5774,3104 C14.1@5775,3105 ; C14.1@5775,3101.54 v4@5858.46,3101.54
  Bottom Layer w40: C11.2 v4(5080,3675)
  other v4: 5860,3100 5585,3105
VCCA_PLL1: C41.1 C42.2 C43.2 FB1.2 U1.27 | length 473.6
  Top Layer w12: v1@4235,3050 4236.1,3051.1 U1.27
  Bottom Layer w12: FB1.2@3855,3055 3860,3050 4065,3050 v1(4240,3050)
VCCA_PLL2: C44.1 C45.2 C46.2 FB2.2 U1.154 | length 477.1
  Top Layer w12: U1.154 v1@3043.9,3051.1
  Bottom Layer w12: v1(3045,3050) 3225,3050 3430,3050 FB2.2@3435,3055
WRN: U1.214 U9.30 | length 984.3
  Top Layer w8: U9.30 3037.81,2149.81 3080,2192 3245,2192 3582,2192 3708.9,2318.9 U1.214
pads on no net: DL1.6 DL1.7 DL1.9 DL1.10 DL1.11 DL1.12 DL2.5 DL2.6 DL2.7 DL2.8 DL2.10 DL2.11 JP2.6 JP2.7 JP2.8 P1.10 P1.15 P1.16 P2.4 P2.10 P2.15 P2.16 S1.3 S1.4 U1.1 U1.2 U1.3 U1.4 U1.5 U1.6 U1.7 U1.8 U1.11 U1.12 U1.18 U1.19 U1.20 U1.21 U1.23 U1.28 U1.38 U1.39 U1.41 U1.42 U1.43 U1.48 U1.49 U1.50 U1.53 U1.54 U1.55 U1.56 U1.61 U1.62 U1.63 U1.64 U1.65 U1.66 U1.67 U1.68 U1.73 U1.74 U1.75 U1.76 U1.77 U1.78 U1.79 U1.82 U1.83 U1.84 U1.85 U1.86 U1.87 U1.88 U1.93 U1.94 U1.95 U1.98 U1.99 U1.100 U1.101 U1.104 U1.105 U1.106 U1.107 U1.108 U1.113 U1.114 U1.115 U1.116 U1.117 U1.118 U1.119 U1.120 U1.121 U1.122 U1.123 U1.124 U1.125 U1.126 U1.127 U1.128 U1.131 U1.134 U1.135 U1.136 U1.137 U1.138 U1.139 U1.143 U1.144 U1.152 U1.153 U1.156 U1.158 U1.159 U1.163 U1.164 U1.165 U1.169 U1.170 U1.173 U1.174 U1.175 U1.176 U1.177 U1.178 U1.179 U1.180 U1.208 U1.225 U1.226 U1.227 U1.228 U1.233 U1.234 U1.235 U1.236 U1.237 U1.238 U1.239 U1.240 U5.1 U6.1 U9.14 U9.37 U9.38 U9.39 U9.40 U9.45 U9.46 U9.47 U9.48 U9.56

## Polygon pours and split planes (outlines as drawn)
GND on GROUND (split plane): 5899.9,1795.1 2015.1,1795.1 2015.1,3844.9 5899.9,3844.9
V3.3 on VCC (split plane): 4344.93,3546.24 4278.76,3480.07 4140.07,3480.07 4140.07,3685 4139.78,3687.94 4138.93,3690.77 4137.53,3693.37 4135.66,3695.66 4130.66,3700.66 4128.37,3702.53 4125.77,3703.93 4122.94,3704.78 4120,3705.07 3150,3705.07 3147.06,3704.78 3144.23,3703.93 3141.63,3702.53 3139.34,3700.66 3137.47,3698.37 3136.07,3695.77 3135.22,3692.94 3134.93,3690 3134.93,3430 3135.22,3427.06 3136.07,3424.23 3137.47,3421.63 3139.34,3419.34 3279.34,3279.34 3314.93,3243.76 3314.93,3051.24 3159.34,2895.66 3157.47,2893.37 3156.07,2890.77 3155.22,2887.94 3154.93,2885 3154.93,2560 3155.22,2557.06 3156.07,2554.23 3157.47,2551.63 3159.34,2549.34 3164.34,2544.34 3166.63,2542.47 3169.23,2541.07 3172.06,2540.22 3175,2539.93 4070,2539.93 4072.94,2540.22 4075.77,2541.07 4078.37,2542.47 4080.66,2544.34 4082.53,2546.63 4083.93,2549.23 4084.78,2552.06 4085.07,2555 4085.07,2878.76 4576.24,3369.93 5188.76,3369.93 5504.34,3054.34 5506.63,3052.47 5509.23,3051.07 5512.06,3050.22 5515,3049.93 5644.93,3049.93 5644.93,2551.24 5473.76,2380.07 4185,2380.07 4182.06,2379.78 4179.23,2378.93 4176.63,2377.53 4174.34,2375.66 4172.47,2373.37 4171.07,2370.77 4170.22,2367.94 4169.93,2365 4169.93,1795.1 2015.1,1795.1 2015.1,3844.9 4344.93,3844.9
V5 on VCC (split plane): 5899.9,1795.1 4200.07,1795.1 4200.07,2349.93 5480,2349.93 5482.94,2350.22 5485.77,2351.07 5488.37,2352.47 5490.66,2354.34 5670.66,2534.34 5672.53,2536.63 5673.93,2539.23 5674.78,2542.06 5675.07,2545 5675.07,3065 5674.78,3067.94 5673.93,3070.77 5672.53,3073.37 5670.66,3075.66 5668.37,3077.53 5665.77,3078.93 5662.94,3079.78 5660,3080.07 5521.24,3080.07 5205.66,3395.66 5203.37,3397.53 5200.77,3398.93 5197.94,3399.78 5195,3400.07 4770.07,3400.07 4770.07,3844.9 5899.9,3844.9
V1.5 on VCC (split plane): 4739.93,3400.07 4570,3400.07 4567.06,3399.78 4564.23,3398.93 4561.63,3397.53 4559.34,3395.66 4059.34,2895.66 4057.47,2893.37 4056.07,2890.77 4055.22,2887.94 4054.93,2885 4054.93,2570.07 3185.07,2570.07 3185.07,2878.76 3340.66,3034.34 3342.53,3036.63 3343.93,3039.23 3344.78,3042.06 3345.07,3045 3345.07,3250 3344.78,3252.94 3343.93,3255.77 3342.53,3258.37 3340.66,3260.66 3300.66,3300.66 3165.07,3436.24 3165.07,3674.93 4109.93,3674.93 4109.93,3465 4110.22,3462.06 4111.07,3459.23 4112.47,3456.63 4114.34,3454.34 4116.63,3452.47 4119.23,3451.07 4122.06,3450.22 4125,3449.93 4285,3449.93 4287.94,3450.22 4290.77,3451.07 4293.37,3452.47 4295.66,3454.34 4370.66,3529.34 4372.53,3531.63 4373.93,3534.23 4374.78,3537.06 4375.07,3540 4375.07,3844.9 4739.93,3844.9

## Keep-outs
Keep-Out Layer:
  the board outline again, w20

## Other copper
VCC (plane layer: these items are gaps in the copper):
  lines w30: 3263,2555 4070,2555 4070,2885 4570,3385 4755,3385 4755,3860 ; 3285,2555 3175,2555 3170,2560 3170,2885 3330,3045 3330,3250 3290,3290 3150,3430 3150,3690 4120,3690 4125,3685 4125,3465 4285,3465 4360,3540 4360,3855 ; 4185,1770 4185,2365 5480,2365 5660,2545 5660,3065 5515,3065 5195,3385 ; 4730,3385 5195,3385 ; 5150,3385 5195,3385

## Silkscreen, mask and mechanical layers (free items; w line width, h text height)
Top Overlay:
  circle w10: c2178.43,1955.79 r78.74
  circle w10: c2178.43,3680.79 r78.74
  circle w10: c5733.43,3680.79 r78.74
  circle w10: c5733.43,1955.79 r78.74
